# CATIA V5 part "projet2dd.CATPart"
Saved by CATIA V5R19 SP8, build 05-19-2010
Part number: projet2d
Bounding box of the stored display mesh (mm): x 0 to 44, y -50 to 136, z -35 to 35
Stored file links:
  U:\projet 2 vendredi\projet2\projet2dd.CATPart
  C:\Documents and Settings\msamadi\Bureau\Nouveau dossier\Product1.CATProduct
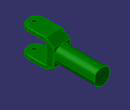
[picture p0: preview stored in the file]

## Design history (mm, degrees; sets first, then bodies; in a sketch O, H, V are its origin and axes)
Parameters
  LENGTH = 10 mm
Body1 (main body)
  Sketch1 on yz-plane, origin (0, 0, 0), H (0, 1, 0), V (0, 0, 1)
    line L1 (-50, 25) -> (15, 25)
    line L2 (15, 25) -> (15, -25)
    line L3 (15, -25) -> (-50, -25)
    line L4 (-50, -25) -> (-50, -35)
    line L5 (-50, -35) -> (15, -35)
    line L6 (15, -35) -> (36, -22)
    point P7 (36, -22)
    line L7 (36, -22) -> (36, 22)
    point P8 (36, 22)
    line L8 (36, 22) -> (15, 35)
    point P9 (15, 35)
    line L9 (15, 35) -> (-50, 35)
    point P10 (-50, 35)
    line L10 (-50, 35) -> (-50, 25)
    length L7 = 44 {= LENGTH *4.4}
    distance L3 L1 = 50 {= LENGTH *5}
    distance L3 H = 25 {= LENGTH *2.5}
    distance L5 H = 35 {= LENGTH *3.5}
    distance L2 V = 15 {= LENGTH *1.5}
    distance L7 V = 36 {= LENGTH *3.6}
    distance P8 L9 = 13 {= LENGTH *1.3}
    length L9 = 65 {= LENGTH *6.5}
    length L5 = 65 {= LENGTH *6.5}
    distance P7 H = 22 {= LENGTH *2.2}
    horizontal: L1 H, L3 H, L5 H, L9 H
    vertical: L2 V, L4 V, L7 V, L10 V
    coincidence: P9 L2, P10 L4, L10 L4
  Pad1: profile Sketch1, direction (1, 0, 0), length 44 {= LENGTH *4.4}
  Sketch2 on face of Pad1 from Sketch1.L9, origin (32.3992, -3.637, 35), H (1, 0, 0), V (0, 1, 0)
    point P1 (-10.3992, -30)
    reference projected line E1 (-32.3992, 18.637) -> (-32.3992, -46.363) from edge [start face of Pad1 | face of Pad1 from Sketch1.L9]
    distance P1 E1 = 22 {= LENGTH *2.2}
    distance H P1 = 30 {= LENGTH *3}
  Hole1: placed by Sketch2, at (22, -33.637, 35) direction (0, 0, -1), diameter 10 {= LENGTH *1}, through (limit type 3), offset 0 {= LENGTH *0}
  Fillet1: radius 22 {= LENGTH *2.2}, on edge [start face of Pad1 | face of Pad1 from Sketch1.L4]
  Fillet2: radius 22 {= LENGTH *2.2}, on edge [face of Pad1 from Sketch1.L4 | end face of Pad1]
  Fillet3: radius 22 {= LENGTH *2.2}, on edge [start face of Pad1 | face of Pad1 from Sketch1.L10]
  Fillet4: radius 22 {= LENGTH *2.2}, on edge [face of Pad1 from Sketch1.L10 | end face of Pad1]
  Sketch3 on face of Pad1 from Sketch1.L7, origin (0, 36, 0), H (-1, 0, 0), V (0, 0, 1)
    circle A1 centre (-22, 0) radius 20
    point P1 (-22, 0)
    distance P1 V = 22 {= LENGTH *2.2}
    distance P1 A1 = 20 {= LENGTH *2}
    coincidence: P1 H
  Pad2: profile Sketch3, direction (0, 1, 0), length 100 {= LENGTH *10}
  Sketch4 on face of Pad1 from Sketch1.L7, origin (0, 36, 0), H (-1, 0, 0), V (0, 0, 1)
    reference projected line E1 (0, 22) -> (-42, 22) from edge [face of Pad1 from Sketch1.L8 | face of Pad1 from Sketch1.L7]
    reference projected line E2 (0, -30) -> (0, 30) from Sketch1
    angle E1 E2 = 90 (reference)
  Fillet5: radius 2 {= LENGTH *0.2}, on start face of Pad1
